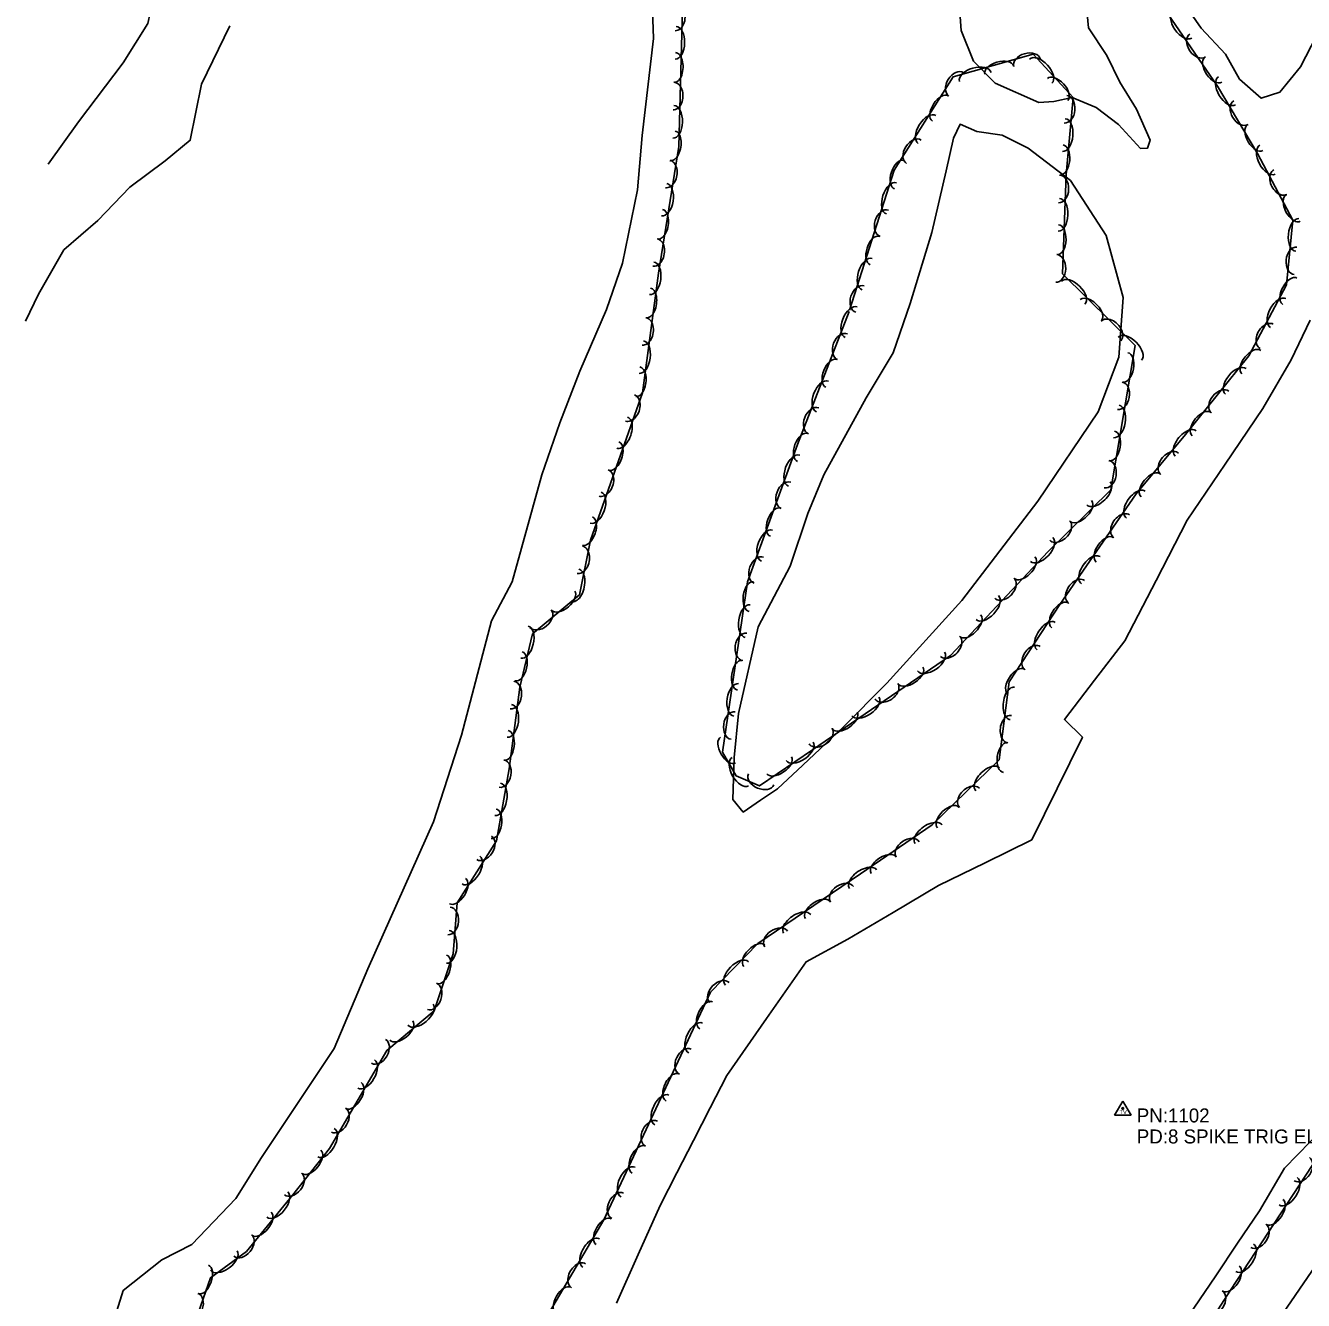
# Model space of a CAD drawing. Extents: x 1451369 to 1458940, y 1868647 to 1875095.
# Drawn here: x 1454408.5 to 1454865, y 1872001.9 to 1872457.2 of the extents above; entities that cross this region are included whole.
import ezdxf

# ---------------------------------------------------------------- set-up
doc = ezdxf.new("R2010")
doc.units = 0
for name, color, linetype in [('E_ROW Point Number', 7, 'Continuous'), ('E_Station Offset', 7, 'Continuous'), ('E_Tract Residual', 7, 'Continuous'), ('S_EDGE_PAVEMENT', 7, 'Continuous'), ('S_EXIST_ROW', 7, 'Continuous'), ('S_SECONDARY_CTL_ANNOT', 7, 'Continuous')]:
    doc.layers.add(name, color=color, linetype=linetype)

msp = doc.modelspace()

# ---------------------------------------------------------------- linework, layer by layer
at = {"layer": 'E_ROW Point Number'}
for points in [[(1454643.17, 1872463.3), (1454641.82, 1872414.02), (1454634.56, 1872368.77), (1454628.86, 1872326.02), (1454622.46, 1872307.77), (1454610.32, 1872273.45), (1454606.43, 1872253.93), (1454589.61, 1872239.94), (1454585.07, 1872220.9), (1454581.23, 1872191.75), (1454576.78, 1872166.07), (1454562.67, 1872143.92), (1454561.25, 1872125.61), (1454554.45, 1872105.31), (1454537.56, 1872091.16), (1454517.07, 1872056.1), (1454504, 1872039.59), (1454487.44, 1872019.37), (1454474.53, 1872009.99), (1454468.45, 1871992.6)], [(1454579.81, 1871970.72), (1454615.08, 1872030.7), (1454653.2, 1872112), (1454670.13, 1872129.39), (1454706.71, 1872154.26), (1454732.35, 1872171.76), (1454756.26, 1872194.93), (1454759.85, 1872222.8), (1454778.01, 1872250.44), (1454805.18, 1872290.01), (1454822.84, 1872311.15), (1454845.45, 1872339.24), (1454858.96, 1872364.59), (1454861.21, 1872387.68), (1454848.61, 1872411.56), (1454834.27, 1872435.54), (1454815.29, 1872463.31)], [(1454702.82, 1872355.55), (1454718.84, 1872405.51), (1454739.85, 1872438.86), (1454768.46, 1872447), (1454782.73, 1872431.5), (1454780.29, 1872404.02), (1454778.97, 1872368.57), (1454804.87, 1872342.92), (1454796.17, 1872291.44), (1454773.75, 1872269.4), (1454738.97, 1872232.26), (1454722.4, 1872220.95), (1454689.57, 1872198.55), (1454670.68, 1872185.65), (1454662.31, 1872189.21), (1454657.46, 1872197.66), (1454666.38, 1872258.47), (1454684.22, 1872307.63), (1454702.7, 1872355.14)], [(1454892.72, 1872087.65), (1454838.97, 1872005.51), (1454793.59, 1871935.04)]]:
    msp.add_lwpolyline(points, dxfattribs=at)
for centre, major_axis, ratio, start_param, end_param in [((1454640.71, 1872460.3), (0.17, 4.93), 0.687401, 3.150347, 6.29194), ((1454821.76, 1872457.61), (3.31, -4.85), 0.55004, 3.141593, 6.283185), ((1454640.72, 1872451.08), (0.18, 5.84), 0.551769, 3.146922, 6.288514), ((1454827.2, 1872450.11), (2.8, -4.09), 0.685261, 3.141593, 6.283185), ((1454640.48, 1872442.27), (0.16, 5.32), 0.54236, 3.146754, 6.288347), ((1454766.26, 1872443.9), (-4.77, -1.36), 0.685309, 3.141593, 6.283185), ((1454771.16, 1872440.93), (-3.98, 4.32), 0.550079, 3.141593, 6.283185), ((1454747.75, 1872438.9), (-5.64, -1.61), 0.550079, 3.141593, 6.283185), ((1454756.28, 1872441.33), (-5.14, -1.46), 0.540698, 3.141593, 6.283185), ((1454832.79, 1872441.45), (3.02, -4.41), 0.54066, 3.141593, 6.283185), ((1454740.99, 1872436.2), (-2.64, -4.19), 0.68531, 3.141593, 6.283185), ((1454777.17, 1872434.41), (-3.62, 3.93), 0.540699, 3.141593, 6.283185), ((1454837.7, 1872433.92), (3.01, -5.04), 0.550036, 3.141593, 6.283185), ((1454639.94, 1872432.03), (0.17, 4.93), 0.687401, 3.150347, 6.29194), ((1454735.28, 1872427.62), (-2.85, -4.52), 0.540699, 3.141593, 6.283185), ((1454639.94, 1872422.82), (0.18, 5.84), 0.551769, 3.146922, 6.288514), ((1454779.97, 1872427.33), (0.44, 4.94), 0.685311, 3.141593, 6.283185), ((1454842.68, 1872426.11), (2.54, -4.25), 0.685256, 3.141593, 6.283185), ((1454730.55, 1872420.12), (-3.13, -4.97), 0.550079, 3.141593, 6.283185), ((1454779.41, 1872418.09), (0.52, 5.85), 0.55008, 3.141593, 6.283185), ((1454639.72, 1872414.28), (0.85, 5.27), 0.540374, 3.144839, 6.286432), ((1454847.74, 1872417.14), (2.74, -4.59), 0.540656, 3.141593, 6.283185), ((1454725.83, 1872412.15), (-2.64, -4.19), 0.68531, 3.141593, 6.283185), ((1454778.63, 1872409.26), (0.47, 5.33), 0.540699, 3.141593, 6.283185), ((1454852.18, 1872409.33), (2.74, -5.19), 0.550033, 3.14159, 6.283182), ((1454637.83, 1872404.17), (0.8, 4.88), 0.684892, 3.147079, 6.288672), ((1454720.56, 1872403.95), (-1.63, -5.09), 0.540699, 3.141593, 6.283185), ((1454856.73, 1872401.26), (2.31, -4.38), 0.685252, 3.141588, 6.283181), ((1454636.62, 1872395), (0.94, 5.78), 0.549748, 3.144944, 6.286536), ((1454717.86, 1872395.51), (-1.79, -5.59), 0.550079, 3.141593, 6.283185), ((1454777.72, 1872398.88), (0.18, 4.95), 0.685311, 3.141593, 6.283185), ((1454861.31, 1872392.03), (2.5, -4.73), 0.540653, 3.14159, 6.283183), ((1454635.22, 1872386.26), (0.85, 5.27), 0.540374, 3.144839, 6.286432), ((1454715.28, 1872386.61), (-1.51, -4.72), 0.68531, 3.141593, 6.283185), ((1454777.63, 1872389.62), (0.22, 5.86), 0.55008, 3.141593, 6.283185), ((1454862.83, 1872382.43), (-0.57, -5.84), 0.550015, 3.141593, 6.283185), ((1454711.88, 1872376.88), (-1.63, -5.09), 0.540699, 3.141593, 6.283185), ((1454777.3, 1872380.75), (0.2, 5.34), 0.540699, 3.141593, 6.283185), ((1454633.33, 1872376.15), (0.8, 4.88), 0.684892, 3.147079, 6.288672), ((1454862.19, 1872373.19), (-0.48, -4.93), 0.685231, 3.141593, 6.283185), ((1454709.18, 1872368.44), (-1.79, -5.59), 0.550079, 3.141593, 6.283185), ((1454776.66, 1872370.47), (0.18, 4.95), 0.685311, 3.141593, 6.283185), ((1454632.18, 1872366.92), (0.78, 5.81), 0.549666, 3.144715, 6.286307), ((1454706.6, 1872359.54), (-1.51, -4.72), 0.68531, 3.141593, 6.283185), ((1454782.77, 1872361.82), (-4.17, 4.13), 0.550097, 3.141586, 6.283178), ((1454860.16, 1872362.33), (-2.51, -4.72), 0.540647, 3.14159, 6.283183), ((1454631.01, 1872358.15), (0.71, 5.29), 0.540293, 3.144617, 6.28621), ((1454789.07, 1872355.58), (-3.8, 3.76), 0.540716, 3.141586, 6.283179), ((1454855.99, 1872354.51), (-2.76, -5.18), 0.550026, 3.14159, 6.283182), ((1454703.45, 1872351.23), (-2.13, -5.47), 0.550079, 3.141593, 6.283185), ((1454629.39, 1872347.98), (0.67, 4.9), 0.68479, 3.146704, 6.288297), ((1454796.21, 1872348.15), (-3.52, 3.49), 0.685332, 3.141581, 6.283174), ((1454851.86, 1872346.21), (-2.33, -4.37), 0.685244, 3.141588, 6.283181), ((1454700.34, 1872342.51), (-1.8, -4.62), 0.68531, 3.141593, 6.283185), ((1454802.97, 1872341.82), (-4.17, 4.13), 0.550097, 3.141586, 6.283178), ((1454628.43, 1872338.79), (0.78, 5.81), 0.549666, 3.144715, 6.286307), ((1454846.39, 1872337.03), (-3.35, -4.16), 0.540657, 3.141593, 6.283185), ((1454696.36, 1872333), (-1.94, -4.98), 0.540699, 3.141593, 6.283185), ((1454801.4, 1872335.1), (0.89, 5.27), 0.540699, 3.141593, 6.283185), ((1454627.26, 1872330.01), (0.71, 5.29), 0.540293, 3.144617, 6.28621), ((1454840.83, 1872330.12), (-3.68, -4.57), 0.550037, 3.141593, 6.283185), ((1454693.15, 1872324.74), (-2.13, -5.47), 0.550079, 3.141593, 6.283185), ((1454799.43, 1872324.99), (0.83, 4.89), 0.685311, 3.141593, 6.283185), ((1454835.23, 1872322.74), (-3.11, -3.86), 0.685257, 3.141593, 6.283185), ((1454624.45, 1872320.63), (1.64, 4.67), 0.683488, 3.142625, 6.284218), ((1454690.03, 1872316.01), (-1.8, -4.62), 0.68531, 3.141593, 6.283185), ((1454798.14, 1872315.81), (0.98, 5.79), 0.55008, 3.141593, 6.283185), ((1454828.57, 1872314.88), (-3.35, -4.16), 0.540657, 3.141593, 6.283185), ((1454621.63, 1872311.81), (1.94, 5.54), 0.548617, 3.142224, 6.283817), ((1454686.08, 1872306.55), (-1.82, -5.03), 0.540699, 3.141593, 6.283185), ((1454796.66, 1872307.07), (0.89, 5.27), 0.540699, 3.141593, 6.283185), ((1454822.95, 1872307.97), (-3.76, -4.5), 0.550038, 3.14159, 6.283183), ((1454618.69, 1872303.45), (1.78, 5.04), 0.539228, 3.141662, 6.283255), ((1454817.21, 1872300.7), (-3.18, -3.8), 0.685259, 3.141588, 6.283181), ((1454683.05, 1872298.21), (-2, -5.52), 0.550079, 3.141593, 6.283185), ((1454794.69, 1872296.95), (0.83, 4.89), 0.685311, 3.141593, 6.283185), ((1454615.01, 1872293.83), (1.65, 4.67), 0.683446, 3.14171, 6.283303), ((1454810.41, 1872292.96), (-3.43, -4.1), 0.540658, 3.14159, 6.283183), ((1454680.14, 1872289.42), (-1.69, -4.66), 0.68531, 3.141593, 6.283185), ((1454791.78, 1872290.1), (4.18, 4.11), 0.550088, 3.141599, 6.283192), ((1454805.09, 1872286.13), (-3.32, -4.84), 0.550038, 3.141547, 6.28314), ((1454612.17, 1872285.01), (1.96, 5.53), 0.548583, 3.141665, 6.283257), ((1454785.46, 1872283.88), (3.81, 3.75), 0.540708, 3.141599, 6.283192), ((1454676.38, 1872279.83), (-1.82, -5.03), 0.540699, 3.141593, 6.283185), ((1454800.06, 1872278.35), (-2.8, -4.09), 0.685258, 3.141518, 6.283111), ((1454609.21, 1872276.65), (1.78, 5.04), 0.539228, 3.141662, 6.283255), ((1454673.36, 1872271.49), (-2, -5.52), 0.550079, 3.141593, 6.283185), ((1454777.93, 1872276.85), (3.53, 3.47), 0.685321, 3.141604, 6.283197), ((1454771.48, 1872270.08), (4.01, 4.28), 0.550079, 3.141594, 6.283186), ((1454794.02, 1872270), (-3.03, -4.41), 0.540658, 3.141549, 6.283141), ((1454606.5, 1872266.41), (0.97, 4.86), 0.68359, 3.141696, 6.283289), ((1454789, 1872262.69), (-3.32, -4.84), 0.550038, 3.141547, 6.28314), ((1454670.44, 1872262.7), (-1.69, -4.66), 0.68531, 3.141593, 6.283185), ((1454765.42, 1872263.61), (3.65, 3.9), 0.540699, 3.141593, 6.283186), ((1454604.94, 1872257.28), (1.15, 5.76), 0.548699, 3.141656, 6.283249), ((1454758.19, 1872256.26), (3.39, 3.62), 0.68531, 3.141594, 6.283187), ((1454783.97, 1872254.91), (-2.8, -4.09), 0.685258, 3.141518, 6.283111), ((1454600.56, 1872251.8), (4.11, 3.42), 0.539329, 3.141593, 6.283185), ((1454667.76, 1872253.28), (-0.78, -5.29), 0.540699, 3.141593, 6.283185), ((1454666.47, 1872244.5), (-0.85, -5.81), 0.55008, 3.141593, 6.283185), ((1454752.05, 1872249.33), (4.01, 4.28), 0.550079, 3.141594, 6.283186), ((1454778.01, 1872246.56), (-2.94, -4.47), 0.540654, 3.14156, 6.283153), ((1454592.48, 1872245.41), (3.81, 3.17), 0.683574, 3.141593, 6.283185), ((1454745.99, 1872242.86), (3.65, 3.9), 0.540699, 3.141593, 6.283186), ((1454586.73, 1872236.97), (1.36, 5.71), 0.548663, 3.141593, 6.283185), ((1454773.14, 1872239.15), (-3.22, -4.9), 0.550034, 3.141559, 6.283152), ((1454665.39, 1872235.3), (-0.72, -4.9), 0.685311, 3.141593, 6.283185), ((1454738.76, 1872235.51), (3.39, 3.62), 0.68531, 3.141594, 6.283187), ((1454768.27, 1872231.27), (-2.72, -4.14), 0.685254, 3.141538, 6.283131), ((1454584.67, 1872228.34), (1.24, 5.2), 0.539306, 3.141593, 6.283185), ((1454731.97, 1872230.05), (4.85, 3.31), 0.550079, 3.141593, 6.283185), ((1454663.63, 1872225.15), (-0.78, -5.29), 0.540699, 3.141593, 6.283185), ((1454724.64, 1872225.05), (4.42, 3.01), 0.540698, 3.141593, 6.283185), ((1454762.39, 1872222.81), (-2.94, -4.47), 0.540654, 3.14156, 6.283153), ((1454582.3, 1872218.08), (0.65, 4.91), 0.683678, 3.141593, 6.283185), ((1454662.34, 1872216.37), (-0.85, -5.81), 0.55008, 3.141593, 6.283185), ((1454715.99, 1872219.46), (4.09, 2.79), 0.68531, 3.141589, 6.283182), ((1454761, 1872215.12), (-0.75, -5.82), 0.550123, 3.141354, 6.282947), ((1454581.35, 1872208.87), (0.77, 5.82), 0.548769, 3.141593, 6.283185), ((1454708.49, 1872214.02), (4.85, 3.31), 0.55008, 3.141591, 6.283183), ((1454661.26, 1872207.18), (-0.72, -4.9), 0.685311, 3.141593, 6.283185), ((1454701.16, 1872209.02), (4.42, 3.01), 0.540699, 3.141591, 6.283183), ((1454760.08, 1872205.91), (-0.63, -4.91), 0.685365, 3.141202, 6.282795), ((1454580.19, 1872200.08), (0.7, 5.3), 0.539411, 3.141593, 6.283185), ((1454692.51, 1872203.43), (4.09, 2.79), 0.68531, 3.141589, 6.283182), ((1454659.46, 1872198.43), (2.66, -4.64), 0.540699, 3.141593, 6.283185), ((1454685.01, 1872198), (4.85, 3.31), 0.550079, 3.141593, 6.283185), ((1454758.5, 1872195.73), (-0.68, -5.3), 0.540742, 3.141362, 6.282954), ((1454663.88, 1872190.74), (2.92, -5.09), 0.55008, 3.141593, 6.283185), ((1454677.68, 1872193), (4.42, 3.01), 0.540698, 3.141593, 6.283185), ((1454578.52, 1872190.01), (0.85, 4.88), 0.683621, 3.141593, 6.283185), ((1454752.15, 1872187.99), (-4.21, -4.08), 0.550264, 3.141341, 6.282934), ((1454577.19, 1872180.84), (1, 5.78), 0.548724, 3.141593, 6.283185), ((1454671.27, 1872187.99), (4.56, -1.94), 0.68531, 3.141593, 6.283185), ((1454745.68, 1872181.36), (-3.56, -3.45), 0.68554, 3.14118, 6.282773), ((1454575.68, 1872172.1), (0.91, 5.27), 0.539366, 3.141593, 6.283185), ((1454738.1, 1872174.38), (-3.84, -3.72), 0.54088, 3.141349, 6.282941), ((1454731.14, 1872168.37), (-4.85, -3.31), 0.550055, 3.141591, 6.283184), ((1454572.33, 1872163.51), (2.66, 4.18), 0.683367, 3.141593, 6.283185), ((1454723.64, 1872162.93), (-4.09, -2.79), 0.685281, 3.14159, 6.283182), ((1454567.58, 1872155.56), (3.15, 4.95), 0.54852, 3.141593, 6.283185), ((1454714.99, 1872157.34), (-4.42, -3.01), 0.540675, 3.141591, 6.283184), ((1454707.66, 1872152.34), (-4.85, -3.3), 0.550066, 3.141547, 6.28314), ((1454562.81, 1872148.08), (2.87, 4.51), 0.539166, 3.141593, 6.283185), ((1454700.15, 1872146.92), (-4.1, -2.79), 0.685293, 3.141519, 6.283111), ((1454691.48, 1872141.34), (-4.42, -3.01), 0.540686, 3.141549, 6.283142), ((1454559.78, 1872137.41), (0.38, 4.94), 0.683757, 3.141593, 6.283185), ((1454684.15, 1872136.36), (-4.85, -3.3), 0.550066, 3.141547, 6.28314), ((1454559.33, 1872128.16), (0.45, 5.85), 0.548833, 3.141593, 6.283185), ((1454676.64, 1872130.93), (-4.1, -2.79), 0.685293, 3.141519, 6.283111), ((1454668.82, 1872125.01), (-3.73, -3.83), 0.540663, 3.141593, 6.283185), ((1454557.19, 1872120.14), (1.7, 5.07), 0.539238, 3.141593, 6.283185), ((1454662.64, 1872118.66), (-4.09, -4.2), 0.550043, 3.141593, 6.283185), ((1454553.67, 1872110.45), (1.57, 4.7), 0.683459, 3.141593, 6.283185), ((1454656.36, 1872111.84), (-3.46, -3.55), 0.685265, 3.141593, 6.283185), ((1454651.63, 1872103.67), (-2.27, -4.84), 0.540649, 3.141547, 6.28314), ((1454549.55, 1872103.96), (4.5, 3.77), 0.548683, 3.141593, 6.283185), ((1454542.75, 1872098.26), (4.1, 3.43), 0.539326, 3.141593, 6.283185), ((1454647.87, 1872095.64), (-2.49, -5.31), 0.550029, 3.141546, 6.283138), ((1454534.62, 1872090.83), (2.5, 4.28), 0.683367, 3.141593, 6.283185), ((1454644.17, 1872087.15), (-2.1, -4.49), 0.685247, 3.141516, 6.283108), ((1454530.17, 1872082.71), (2.96, 5.07), 0.548519, 3.141593, 6.283185), ((1454639.56, 1872077.93), (-2.27, -4.84), 0.540649, 3.141547, 6.28314), ((1454525.7, 1872075.05), (2.7, 4.62), 0.539166, 3.141593, 6.283185), ((1454635.8, 1872069.9), (-2.49, -5.31), 0.550029, 3.141546, 6.283138), ((1454520.27, 1872066.29), (2.5, 4.28), 0.683367, 3.141593, 6.283185), ((1454515.83, 1872058.17), (2.96, 5.07), 0.548519, 3.141593, 6.283185), ((1454632.11, 1872061.41), (-2.1, -4.49), 0.685247, 3.141516, 6.283108), ((1454510.62, 1872051.37), (3.32, 4.19), 0.53919, 3.141593, 6.283185), ((1454627.5, 1872052.19), (-2.27, -4.84), 0.540649, 3.141547, 6.28314), ((1454623.73, 1872044.16), (-2.49, -5.31), 0.550029, 3.141546, 6.283138), ((1454864.42, 1872048.75), (2.71, 4.15), 0.68525, 3.141593, 6.283185), ((1454504.03, 1872043.45), (3.08, 3.89), 0.683397, 3.141593, 6.283185), ((1454859.56, 1872040.86), (3.21, 4.91), 0.550031, 3.141593, 6.283185), ((1454498.42, 1872036.12), (3.72, 4.54), 0.548551, 3.141593, 6.283185), ((1454620.04, 1872035.67), (-2.1, -4.49), 0.685247, 3.141516, 6.283108), ((1454854.71, 1872033.44), (2.93, 4.47), 0.540652, 3.141593, 6.283185), ((1454492.81, 1872029.26), (3.39, 4.14), 0.539196, 3.141593, 6.283185), ((1454615.03, 1872026.44), (-2.71, -4.61), 0.540792, 3.141353, 6.282945), ((1454848.85, 1872024.96), (2.71, 4.15), 0.68525, 3.141593, 6.283185), ((1454486.08, 1872021.45), (3.14, 3.83), 0.683406, 3.141593, 6.283185), ((1454610.54, 1872018.8), (-2.97, -5.06), 0.550174, 3.141345, 6.282938), ((1454844, 1872017.07), (3.21, 4.91), 0.550031, 3.141593, 6.283185), ((1454479.32, 1872016.08), (4.75, 3.45), 0.548754, 3.141593, 6.283185), ((1454472.07, 1872009.35), (1.77, 5.05), 0.53923, 3.141593, 6.283185), ((1454606.07, 1872010.68), (-2.51, -4.27), 0.685428, 3.141187, 6.28278), ((1454839.14, 1872009.65), (2.93, 4.47), 0.540652, 3.141593, 6.283185), ((1454468.42, 1871999.71), (1.64, 4.68), 0.683448, 3.141593, 6.283185), ((1454600.63, 1872001.94), (-2.71, -4.61), 0.540792, 3.141353, 6.282945), ((1454833.31, 1872001.13), (2.68, 4.17), 0.68525, 3.141593, 6.283185)]:
    msp.add_ellipse(centre, major_axis=major_axis, ratio=ratio, start_param=start_param, end_param=end_param, dxfattribs=at)
at = {"layer": 'E_Station Offset'}
for p, q in [((1454800.46, 1872073.04), (1454797.45, 1872068.09)), ((1454800.46, 1872073.04), (1454803.41, 1872068.09)), ((1454797.45, 1872068.09), (1454803.41, 1872068.09))]:
    msp.add_line(p, q, dxfattribs=at)
for radius in [0.311, 0.183, 0.103]:
    msp.add_circle((1454800.46, 1872070.43), radius, dxfattribs=at)
at = {"layer": 'E_Tract Residual'}
for points in [[(1454544.61, 1872720.71), (1454529.54, 1872700.16), (1454520.55, 1872686.3), (1454507.21, 1872659.67), (1454500.37, 1872634.92), (1454499.5, 1872617.37), (1454505.39, 1872593.58), (1454513.63, 1872576.49), (1454521.63, 1872562.12), (1454520.92, 1872546.28), (1454504.3, 1872531.32), (1454480.86, 1872515.33), (1454467.85, 1872506.02), (1454459.36, 1872491.68), (1454455.5, 1872473.29), (1454452.18, 1872457.93), (1454443.34, 1872443.88), (1454427.44, 1872422.78), (1454416.56, 1872407.67)], [(1454631.29, 1872496.91), (1454632.82, 1872452.61), (1454628.81, 1872418), (1454627.09, 1872398.6), (1454621.7, 1872372.32), (1454616.01, 1872355.75), (1454606.45, 1872333.77), (1454599.3, 1872315.35), (1454592.97, 1872296.79), (1454582.28, 1872258.57), (1454574.96, 1872244.62), (1454564.18, 1872203.71), (1454554.2, 1872172.82), (1454530.73, 1872120.35), (1454518.77, 1872091.83), (1454492.76, 1872052.95), (1454483.58, 1872038.22), (1454467.84, 1872021.78), (1454457.14, 1872016.35), (1454443.33, 1872005.36), (1454439.97, 1871994.36)], [(1454787.51, 1872463.96), (1454788.26, 1872456.42), (1454794.7, 1872446.47), (1454799.35, 1872437.04), (1454805.32, 1872427.38), (1454810.26, 1872416.33), (1454809.23, 1872413.39), (1454806.77, 1872413.33), (1454798.87, 1872421.92), (1454790.96, 1872427.93), (1454782.38, 1872431.56), (1454775.8, 1872430.05), (1454770.49, 1872429.7), (1454754.88, 1872436.7), (1454747.16, 1872444.51), (1454742.7, 1872455.43), (1454741.94, 1872467.02)], [(1454869.64, 1872453.51), (1454863.9, 1872442.52), (1454856.57, 1872433.46), (1454849.91, 1872431.24), (1454842.15, 1872438.13), (1454837.14, 1872447.04), (1454828.44, 1872456.27), (1454824.67, 1872461.74)], [(1454481.5, 1872457.12), (1454471.33, 1872436.32), (1454467.32, 1872416.23), (1454458.37, 1872408.95), (1454445.69, 1872399.55), (1454434.29, 1872387.53), (1454422.14, 1872377.07), (1454413.09, 1872361.29), (1454408.5, 1872351.68)], [(1454700.53, 1872206.56), (1454686.11, 1872193.09), (1454677.09, 1872184.64), (1454671.01, 1872180.49), (1454664.89, 1872176.31), (1454661.12, 1872180.79), (1454661.68, 1872195.74), (1454663.2, 1872211.47), (1454670.24, 1872242.41), (1454681.61, 1872264.12), (1454687.93, 1872282.91), (1454693.65, 1872296.72), (1454708.84, 1872324.2), (1454718.41, 1872340.31), (1454724.56, 1872357.93), (1454732.29, 1872383.31), (1454737.39, 1872405.37), (1454739.96, 1872416.95), (1454742.32, 1872421.95), (1454748.28, 1872419.43), (1454757.38, 1872418.08), (1454766.6, 1872413.38), (1454781.73, 1872401.88), (1454794.47, 1872382.23), (1454800.55, 1872360.11), (1454799.01, 1872338.78), (1454791.63, 1872319.23), (1454770.16, 1872287.29), (1454743, 1872251.89), (1454716.15, 1872222.37), (1454700.26, 1872206.26)], [(1454867.36, 1872352.01), (1454860.57, 1872337.84), (1454850.53, 1872320.43), (1454837.02, 1872300.5), (1454823.51, 1872280.57), (1454812.34, 1872259.03), (1454801.16, 1872237.5), (1454790.38, 1872223.43), (1454779.61, 1872209.36), (1454786.01, 1872203.06), (1454776.97, 1872184.7), (1454767.92, 1872166.34), (1454751.26, 1872158.2), (1454734.59, 1872150.07), (1454718.4, 1872140.47), (1454702.21, 1872130.87), (1454687.33, 1872122.82), (1454673.15, 1872102.53), (1454658.96, 1872082.24), (1454653.01, 1872070.62), (1454647.05, 1872059), (1454641.1, 1872047.39), (1454635.14, 1872035.77), (1454627.35, 1872018.31), (1454619.56, 1872000.84)]]:
    msp.add_lwpolyline(points, dxfattribs=at)
at = {"layer": 'S_EDGE_PAVEMENT'}
msp.add_lwpolyline([(1454869.28, 1872014.16), (1454856.27, 1871995.25)], dxfattribs=at)
at = {"layer": 'S_EXIST_ROW'}
for points in [[(1455067.63, 1872351.06), (1455053.98, 1872330.57), (1455040.32, 1872310.08), (1455028.09, 1872291.25), (1455015.85, 1872272.42), (1455003.61, 1872253.59), (1454991.38, 1872234.76), (1454982.74, 1872224.5), (1454974.11, 1872214.23), (1454965.48, 1872203.97), (1454956.84, 1872193.71), (1454945.77, 1872171.92), (1454934.69, 1872150.13), (1454927.44, 1872139.88), (1454920.2, 1872129.63), (1454912.95, 1872119.39), (1454905.71, 1872109.14), (1454898.46, 1872098.89), (1454891.21, 1872088.65), (1454883.97, 1872078.4), (1454876.72, 1872068.15), (1454867.48, 1872058.62), (1454858.23, 1872049.09)], [(1454849.28, 1872033.91), (1454858.23, 1872049.09)], [(1454707.96, 1871838.25), (1454715.68, 1871848.85), (1454723.41, 1871859.46), (1454731.14, 1871870.06), (1454738.87, 1871880.67), (1454747.32, 1871891.31), (1454755.77, 1871901.96), (1454764.23, 1871912.6), (1454772.68, 1871923.25), (1454784.03, 1871939.3), (1454795.39, 1871955.35), (1454806.74, 1871971.41), (1454818.1, 1871987.46), (1454825.89, 1871999.07), (1454833.69, 1872010.69), (1454841.48, 1872022.3), (1454849.28, 1872033.91)]]:
    msp.add_lwpolyline(points, dxfattribs=at)

# ---------------------------------------------------------------- texts
at = {"layer": 'E_Station Offset'}
msp.add_text('TV', height=1.5, rotation=360, dxfattribs=at).set_placement((1454799.25, 1872068.42))
at = {"layer": 'S_SECONDARY_CTL_ANNOT'}
for s, p in [('PN:1102', (1454805.46, 1872065.43)), ('PD:8 SPIKE TRIG ELEV', (1454805.46, 1872057.93))]:
    msp.add_text(s, height=5, dxfattribs=at).set_placement(p)

doc.saveas('drawing.dxf')
